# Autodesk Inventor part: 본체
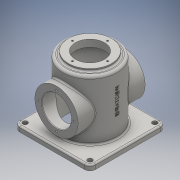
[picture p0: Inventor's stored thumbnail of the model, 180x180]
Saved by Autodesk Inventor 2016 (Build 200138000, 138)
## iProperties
Created: 2019-08
Part Number: 본체
Material: 일반
Document SubType Name: Modeling
Designer: user
Density: 1 g/cm^3
Appearance: 기본값
Author: user
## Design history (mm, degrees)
sketch "스케치1"
  geometry: L1 (-60, -70)-(60, -70); L2 (70, -60)-(70, 60); L3 (60, 70)-(-60, 70); L4 (-70, 60)-(-70, -60); L5 (-70, -70)-(70, 70); L6 (70, -70)-(-70, 70); C1 r 4.5 at (60, 60); C2 r 4.5 at (-60, 60); C3 r 4.5 at (-60, -60); C4 r 4.5 at (60, -60); A1 r 10 centre (-60, 60) between (-60, 70) and (-70, 60); A2 r 10 centre (60, 60) between (70, 60) and (60, 70); A3 r 10 centre (60, -60) between (60, -70) and (70, -60); A4 r 10 centre (-60, -60) between (-70, -60) and (-60, -70); 1 further point
  constraints: 12 end point, 8 centre point, 8 point on circle, 8 point on line, 8 tangent, 6 equal radius, 4 coincident, 2 midpoint, 2 parallel, 1 horizontal, 1 perpendicular
  dimensions: "d0" = 140 distance of L5.end L6.end; "d1" = 140 distance of L6.start L5.end; "d2" = 10 radius of A1; "d3" = 9 diameter of C1
extrude "돌출1" new body sketch "스케치1" distance "d4" = 10; taper "d5" = 0 deg
fillet "모깎기1" dims "d6" = 3
sketch "스케치2"
  geometry: C1 r 50 at (0, 0); 1 further point
  constraints: 1 centre point, 1 coincident
  dimensions: "d7" = 100 diameter of C1
extrude "돌출2" join sketch "스케치2" distance "d8" = 110; taper "d9" = 0 deg
fillet "모깎기2" dims "d10" = 5
node "작업 평면1"
sketch "스케치3"
  geometry: L1 (60, 0)-(-60, 0) reference; L2 (-60, 0)-(-70, 0) reference; C1 r 40 at (0, 60); 2 further points
  constraints: 1 centre point, 1 midpoint, 1 vertical alignment
  dimensions: "d12" = 80 diameter of C1; "d13" = 60 distance from line of L2 C1.centre
extrude "돌출3" join sketch "스케치3" distance "d14" = 124; taper "d15" = 0 deg
sketch "스케치4"
  geometry: C1 r 45 at (0, 0); 1 further point
  constraints: 1 centre point, 1 coincident
  dimensions: "d16" = 90 diameter of C1
extrude "돌출4" cut sketch "스케치4" distance "d17" = 112; taper "d18" = 0 deg
fillet "모깎기3" dims "d19" = 3
sketch "스케치5"
  geometry: L1 (-60, -60)-(60, -60) reference; C1 r 27 at (0, 0); C2 r 40 at (0, 0) reference; 2 further points
  constraints: 1 centre point, 1 concentric, 1 midpoint, 1 vertical alignment
  dimensions: "d20" = 54 diameter of C1
extrude "돌출5" cut sketch "스케치5" stored distance "d21" = 112; taper "d22" = 0 deg
sketch "스케치6"
  geometry: C1 r 40 at (0, 0); 1 further point
  constraints: 1 centre point, 1 coincident
  dimensions: "d23" = 80 diameter of C1
extrude "돌출6" join sketch "스케치6" distance "d24" = 5; taper "d25" = 0 deg
fillet "모깎기4" dims "d26" = 3
sketch "스케치7"
  geometry: C1 r 27 at (0, 0); 1 further point
  constraints: 1 centre point, 1 coincident
  dimensions: "d27" = 54 diameter of C1
extrude "돌출7" cut sketch "스케치7" stored distance "d28" = 15; taper "d29" = 0 deg
chamfer "모따기1" distance "d30" = 1; stored, may be unused: second distance "d31" = 2, angle "d32" = 45 deg
sketch "스케치8" dims "d33" = 65
  geometry: L1 (-60, -60)-(60, -60) reference; C1 r 28 at (0, 0) reference; 4 further points
  constraints: 2 vertical alignment, 1 coincident, 1 midpoint, 2 other
hole "구멍1" sketch "스케치8" at (0, 32.5) diameter "d34" = 3.242; stored, may be unused: countersink angle "d38" = 90 deg, drill point angle "d40" = 118 deg; dims "d35" = 8, "d36" = 4, "d37" = 2, "d39" = 10
sketch "스케치9" dims "d44" = 65
  geometry: 3 further points
  constraints: 2 horizontal alignment, 1 coincident, 2 other
hole "구멍2" sketch "스케치9" at (-32.5, 0) diameter "d45" = 3.242; stored, may be unused: countersink angle "d49" = 90 deg, drill point angle "d51" = 118 deg; dims "d46" = 8, "d47" = 4, "d48" = 2, "d50" = 10
node "작업 평면2"
sketch "스케치10" dims "d0" = 140, "d1" = 140, "d2" = 10, "d3" = 9
  geometry: L1 (-60, 0)-(60, 0) reference; 3 further points
  constraints: 1 midpoint, 1 vertical alignment, 1 other
  dimensions: "d56" = 70 distance from line of L1 point (0, 70)
feature "엠보싱1" sketch "스케치10" dims "d0" = 140, "d1" = 140, "d2" = 10, "d3" = 9, "d57" = 0.5, "d58" = 0
node "솔리드1"
pattern_circular "원형 패턴1" dims angle "d42" = 360 deg
mirror "대칭1"
pattern_circular "원형 패턴2" dims angle "d53" = 360 deg
other parameters: "d11" = -62
